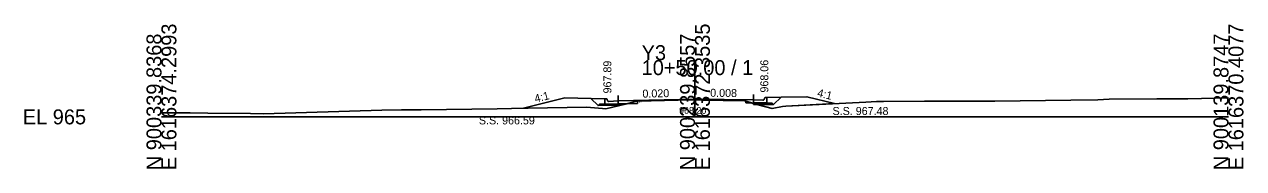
# Model space of a CAD drawing. Extents: x -26 to 203, y -10 to 2017.
# Drawn here: x -25.7 to 202.8, y 490.3 to 517.3 of the extents above; entities that cross this region are included whole.
import ezdxf

# ---------------------------------------------------------------- set-up
doc = ezdxf.new("R2010")
doc.units = 0
for name, color, linetype in [('Default', 7, 'Continuous'), ('Exist Cross Section Cell', 7, 'Continuous'), ('Exist XS Center Line Elevation Label', 7, 'Continuous'), ('Exist XS Ground Line', 7, 'Continuous'), ('Prop XS Dump Level', 7, 'Continuous'), ('Prop XS Earthwork Shape', 7, 'Continuous'), ('Prop XS EOT Tick Mark', 7, 'Continuous'), ('Prop XS Finish Grade', 7, 'Continuous'), ('Prop XS Finish Grade CurbGutter', 7, 'Continuous'), ('Prop XS Finish Grade Earthwork', 7, 'Continuous'), ('Prop XS Finish Grade Pavement', 7, 'Continuous'), ('Prop XS Hydro Elevations', 7, 'Continuous'), ('Prop XS Pvmt Edge Slope', 7, 'Continuous'), ('Prop XS SE Text', 7, 'Continuous'), ('Prop XS Side Slope Text', 7, 'Continuous'), ('Prop XS SS Elevation Text', 7, 'Continuous'), ('Prop XS Subgrade CurbGutter', 7, 'Continuous'), ('Prop XS Subgrade Earthwork', 7, 'Continuous')]:
    doc.layers.add(name, color=color, linetype=linetype)

msp = doc.modelspace()

# ---------------------------------------------------------------- linework, layer by layer
at = {"layer": 'Default'}
msp.add_line((100, 503.3), (111, 503.22), dxfattribs=at)
at = {"layer": 'Exist Cross Section Cell'}
for p, q in [((100, 500), (100, 510.63)), ((0, 500), (100, 500)), ((100, 500), (200, 500))]:
    msp.add_line(p, q, dxfattribs=at)
at = {"layer": 'Exist XS Ground Line'}
for p, q in [((83.28, 501.5), (88.84, 502.85)), ((88.84, 502.85), (89.22, 502.94)), ((89.22, 502.94), (99.39, 503.21)), ((99.39, 503.21), (100, 503.2)), ((100, 503.2), (101.21, 503.16)), ((101.21, 503.16), (109.33, 503)), ((109.33, 503), (111.83, 502.25)), ((132.03, 502.77), (134.04, 502.88)), ((134.04, 502.88), (135.34, 502.9)), ((135.34, 502.9), (143.02, 502.93)), ((143.02, 502.93), (156.19, 502.94)), ((156.19, 502.94), (170.48, 503.16)), ((170.48, 503.16), (175.53, 503.19)), ((175.53, 503.19), (177.65, 503.32)), ((177.65, 503.32), (186.55, 503.36)), ((186.55, 503.36), (192.4, 503.38)), ((192.4, 503.38), (200, 503.54)), ((0, 500.77), (5.39, 500.78)), ((5.39, 500.78), (8.69, 500.68)), ((8.69, 500.68), (16.7, 500.64)), ((16.7, 500.64), (19.13, 500.6)), ((19.13, 500.6), (41.29, 501.27)), ((41.29, 501.27), (44.99, 501.29)), ((44.99, 501.29), (46.26, 501.29)), ((46.26, 501.29), (48.68, 501.33)), ((48.68, 501.33), (62.94, 501.52)), ((62.94, 501.52), (65.59, 501.59)), ((65.59, 501.59), (68.76, 501.63)), ((68.76, 501.63), (79.64, 501.83)), ((79.64, 501.83), (82.67, 501.55)), ((82.67, 501.55), (83.28, 501.5)), ((111.83, 502.25), (114.45, 501.54)), ((114.45, 501.54), (116.41, 501.95)), ((116.41, 501.95), (117.06, 502.03)), ((117.06, 502.03), (132.03, 502.77))]:
    msp.add_line(p, q, dxfattribs=at)
at = {"layer": 'Prop XS Dump Level'}
for p, q in [((100, 503.3), (85.58, 503.01)), ((111, 503.22), (100, 503.3))]:
    msp.add_line(p, q, dxfattribs=at)
at = {"layer": 'Prop XS Earthwork Shape'}
for points in [[(87.24, 502.46), (85.58, 502.43), (85.58, 502.18), (81.83, 502.11), (80.49, 503.45), (75.58, 503.55), (67.87, 501.62), (68.76, 501.63), (79.64, 501.83), (82.67, 501.55), (83.28, 501.5)], [(89.21, 502.5), (87.24, 502.46), (88.84, 502.85), (89.21, 502.94)], [(109.51, 502.6), (110.7, 502.59), (109.51, 502.94)], [(114.75, 502.29), (116.13, 503.67), (121, 503.77), (126.16, 502.48), (117.06, 502.03), (116.41, 501.95), (114.45, 501.54), (111.83, 502.25), (111.55, 502.33)], [(111, 502.58), (111, 502.5), (110.7, 502.59)], [(111, 502.34), (111.55, 502.33), (111, 502.5)]]:
    msp.add_lwpolyline(points, close=True, dxfattribs=at)
at = {"layer": 'Prop XS EOT Tick Mark'}
for p, q in [((85.58, 503.01), (85.58, 504.01)), ((111, 503.22), (111, 504.22))]:
    msp.add_line(p, q, dxfattribs=at)
at = {"layer": 'Prop XS Finish Grade'}
for p, q in [((83.08, 503.39), (80.49, 503.45)), ((113.5, 503.61), (116.13, 503.67))]:
    msp.add_line(p, q, dxfattribs=at)
at = {"layer": 'Prop XS Finish Grade CurbGutter'}
for p, q in [((83.08, 503.39), (83.33, 503.39)), ((83.33, 503.39), (83.46, 503.36)), ((83.55, 503.27), (83.46, 503.36)), ((83.62, 503.02), (83.55, 503.27)), ((83.71, 502.93), (83.62, 503.02)), ((83.83, 502.91), (83.71, 502.93)), ((85.58, 503.01), (83.83, 502.91)), ((111, 503.22), (112.75, 503.12)), ((112.75, 503.12), (112.87, 503.15)), ((112.87, 503.15), (112.97, 503.24)), ((112.97, 503.24), (113.03, 503.49)), ((113.03, 503.49), (113.12, 503.58)), ((113.25, 503.61), (113.12, 503.58)), ((113.5, 503.61), (113.25, 503.61))]:
    msp.add_line(p, q, dxfattribs=at)
at = {"layer": 'Prop XS Finish Grade Earthwork'}
for p, q in [((75.58, 503.55), (67.87, 501.62)), ((80.49, 503.45), (75.58, 503.55)), ((116.13, 503.67), (121, 503.77)), ((121, 503.77), (126.16, 502.48))]:
    msp.add_line(p, q, dxfattribs=at)
at = {"layer": 'Prop XS Finish Grade Pavement'}
for p, q in [((85.58, 503.01), (100, 503.3)), ((100, 503.3), (111, 503.22))]:
    msp.add_line(p, q, dxfattribs=at)
at = {"layer": 'Prop XS Pvmt Edge Slope'}
for p, q in [((82.08, 502.36), (81.83, 502.11)), ((83.08, 502.38), (82.08, 502.36)), ((113.5, 502.61), (114.45, 502.59)), ((114.45, 502.59), (114.75, 502.29))]:
    msp.add_line(p, q, dxfattribs=at)
at = {"layer": 'Prop XS Subgrade CurbGutter'}
for p, q in [((83.08, 502.38), (83.08, 503.39)), ((85.58, 503.01), (85.58, 502.43)), ((111, 503.22), (111, 502.59)), ((113.5, 502.61), (113.5, 503.61)), ((85.58, 502.43), (83.08, 502.38)), ((111, 502.64), (113.5, 502.61))]:
    msp.add_line(p, q, dxfattribs=at)
at = {"layer": 'Prop XS Subgrade Earthwork'}
for p, q in [((81.83, 502.11), (80.49, 503.45)), ((89.21, 502.5), (89.21, 502.94)), ((109.51, 502.6), (109.51, 502.94)), ((114.75, 502.29), (116.13, 503.67)), ((85.58, 502.18), (81.83, 502.11)), ((89.21, 502.5), (85.58, 502.43)), ((85.58, 502.43), (85.58, 502.18)), ((109.51, 502.6), (111, 502.58)), ((111, 502.58), (111, 502.34)), ((111, 502.34), (114.75, 502.29))]:
    msp.add_line(p, q, dxfattribs=at)

# ---------------------------------------------------------------- texts
at = {"layer": 'Exist Cross Section Cell'}
for s, p in [('E 1616374.2993', (2.8, 490)), ('E 1616372.3535', (102.8, 490)), ('E 1616370.4077', (202.8, 490)), ('N 900339.8368', (0, 490)), ('N 900239.8557', (100, 490)), ('N 900139.8747', (200, 490))]:
    msp.add_text(s, height=2.8, rotation=90, dxfattribs=at).set_placement(p)
for s, p in [('Y3', (90, 510.63)), ('10+50.00 / 1', (90, 507.83)), ('EL 965', (-26, 498.6))]:
    msp.add_text(s, height=2.8, dxfattribs=at).set_placement(p)
at = {"layer": 'Exist XS Center Line Elevation Label'}
msp.add_text('968.20', height=1.25, dxfattribs=at).set_placement((97.02, 500.57))
at = {"layer": 'Prop XS Dump Level'}
for p in [(89.21, 502.64), (109.51, 502.64)]:
    msp.add_text('Eop', height=0.3, dxfattribs=at).set_placement(p)
at = {"layer": 'Prop XS Hydro Elevations'}
for s, p in [('967.89', (84.33, 504.39)), ('968.06', (113.75, 504.56))]:
    msp.add_text(s, height=1.5, rotation=90, dxfattribs=at).set_placement(p)
at = {"layer": 'Prop XS SE Text'}
for s, rotation, p in [('0.020', 1.1458, (90.17, 503.6)), ('0.008', 359.2982, (102.85, 503.77))]:
    msp.add_text(s, height=1.5, rotation=rotation, dxfattribs=at).set_placement(p)
at = {"layer": 'Prop XS Side Slope Text'}
for rotation, p in [(345.9638, (122.81, 503.85)), (14.0362, (70.11, 502.66))]:
    msp.add_text('4:1', height=1.5, rotation=rotation, dxfattribs=at).set_placement(p)
at = {"layer": 'Prop XS SS Elevation Text'}
for s, p in [('S.S. 967.48', (125.79, 500.35)), ('S.S. 966.59', (59.5, 498.59))]:
    msp.add_text(s, height=1.5, dxfattribs=at).set_placement(p)

doc.saveas('drawing.dxf')
